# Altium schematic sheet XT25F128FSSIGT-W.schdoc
size 127 x 101 mm
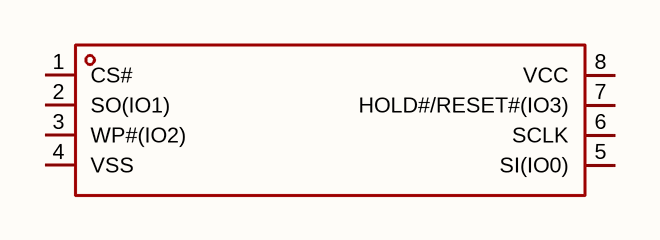
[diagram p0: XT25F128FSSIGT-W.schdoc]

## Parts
U?  xt25f128fssigt-w  [SOP-8_L5.3-W5.3-P1.27-LS8.0-BL]  (value not drawn)

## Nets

Not connected (* = marked no-connect by the designer): U? 1(CS#) 2(SO(IO1)) 3(WP#(IO2)) 4(VSS) 5(SI(IO0)) 6(SCLK) 7(HOLD#/RESET#(IO3)) 8(VCC)

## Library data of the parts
U? = xt25f128fssigt-w: 接口类型:SPI;存储容量:128Mbit;时钟频率(fc):104MHz;; Manufacturer: XTX(芯天下); AddInBom: yes; ModelId: e456afcfff5840a795bdd4917416584f; ModelName: SOP-8_L5.2-W5.3-H2.1-LS7.9-P1.27; ModelTransform: 311.024,204.724,0,90,0,0,0,0.0005,0; Interface: SPI; Clock Frequency: 104MHz; Voltage - Supply: 2.7V~3.6V; Standby Supply Current: 0.5uA; Program / Erase Cycles: 100000次; Page Programming Time (Tpp): 400us; Block Erase Time(tBE): 150ms; Data Retention - TDR (Year): 20年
